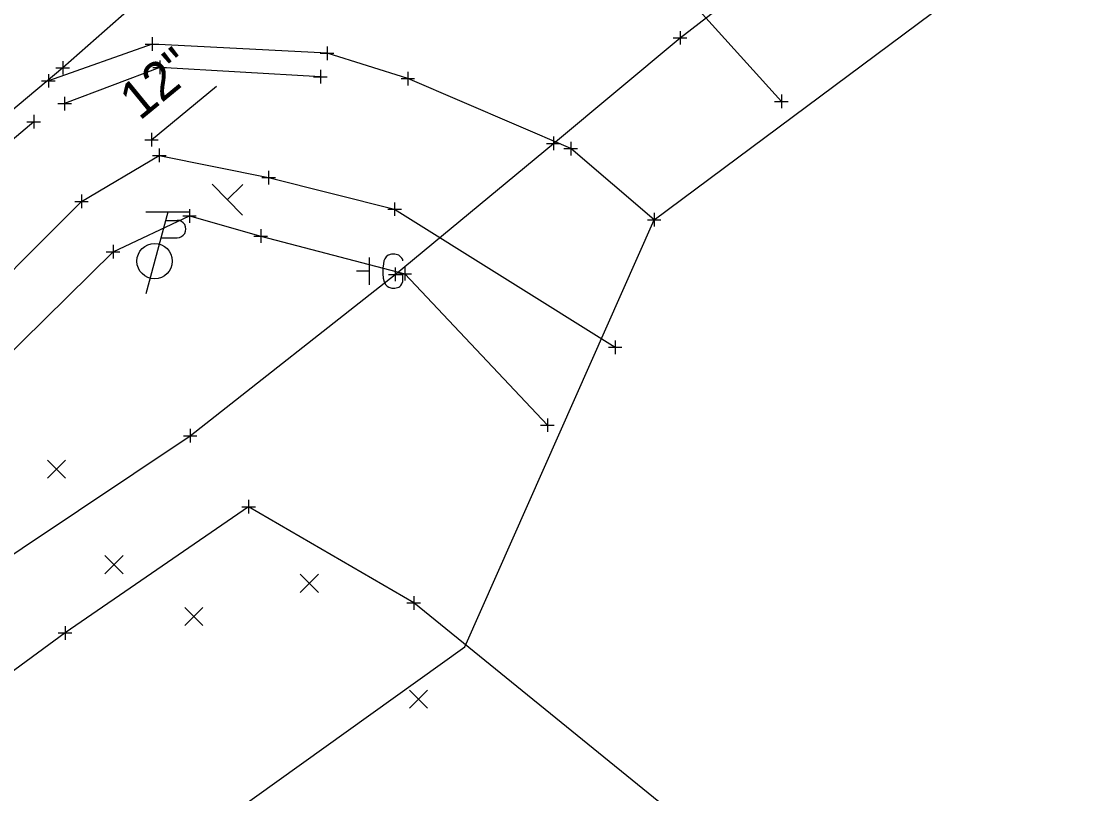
# Model space of a CAD drawing. Extents: x -4 to 139204, y -4 to 477121.
# Drawn here: x 139123.3 to 139201.5, y 476967.4 to 477024.3 of the extents above; entities that cross this region are included whole.
import ezdxf

# ---------------------------------------------------------------- set-up
doc = ezdxf.new("R2010")
doc.units = 0
for name, color, linetype in [('_CIVIL_CONSTRUCTION', 7, 'Continuous'), ('DR_X_Ditch', 7, 'Continuous'), ('DR_X_Storm_Sewer', 7, 'Continuous'), ('DR_X_Text', 7, 'Continuous'), ('DV_X_Property_Line', 7, 'Continuous'), ('GE_X_Alignment', 7, 'Continuous'), ('GE_X_Alignment_100_Bearings', 7, 'Continuous'), ('GE_X_Alignment_100_Cardinal_Points', 7, 'Continuous'), ('GE_X_Alignment_100_Distances', 7, 'Continuous'), ('PV_X_COP', 7, 'Continuous'), ('PV_X_Shoulder', 7, 'Continuous'), ('PV_X_Shoulder_Aggregate', 7, 'Continuous'), ('RD_X_Fence', 7, 'Continuous'), ('SC_Scratch1', 7, 'Continuous'), ('SV_X_Terrain_Boundary', 7, 'Continuous'), ('UT_X_Gas', 7, 'Continuous')]:
    doc.layers.add(name, color=color, linetype=linetype)

msp = doc.modelspace()

# ---------------------------------------------------------------- linework, layer by layer
at = {"layer": '_CIVIL_CONSTRUCTION'}
for p, q in [((139139.571, 477009.978), (139137.337, 477012.268)), ((139138.454, 477011.123), (139139.599, 477012.24))]:
    msp.add_line(p, q, dxfattribs=at)
at = {"layer": 'DR_X_Ditch'}
msp.add_lwpolyline([(139102.91, 476985.845), (139107.6, 476990.771), (139117.961, 477001.241), (139127.724, 477011.001), (139133.449, 477014.389), (139141.493, 477012.75), (139150.77, 477010.429), (139167.005, 477000.273)], dxfattribs=at)
at = {"layer": 'DR_X_Storm_Sewer'}
msp.add_line((139132.876, 477015.536), (139137.671, 477019.471), dxfattribs=at)
at = {"layer": 'DV_X_Property_Line'}
for p, q in [((139148.911, 477004.871), (139148.911, 477006.871)), ((139148.911, 477005.871), (139147.959, 477005.871))]:
    msp.add_line(p, q, dxfattribs=at)
msp.add_lwpolyline([(139151.388, 477006.627), (139151.368, 477006.726), (139151.309, 477006.824), (139151.21, 477006.922), (139151.073, 477007.041), (139150.974, 477007.08), (139150.895, 477007.099), (139150.777, 477007.119), (139150.541, 477007.119), (139150.443, 477007.099), (139150.384, 477007.08), (139150.305, 477007.041), (139150.147, 477006.922), (139150.049, 477006.785), (139149.99, 477006.627), (139149.951, 477006.411), (139149.911, 477006.096), (139149.911, 477005.682), (139149.931, 477005.348), (139150.01, 477005.092), (139150.128, 477004.856), (139150.226, 477004.777), (139150.344, 477004.698), (139150.561, 477004.619), (139150.777, 477004.619), (139150.994, 477004.659), (139151.073, 477004.698), (139151.151, 477004.737), (139151.23, 477004.816), (139151.309, 477004.934), (139151.388, 477005.112), (139151.388, 477005.604), (139150.974, 477005.604)], dxfattribs=at)
at = {"layer": 'GE_X_Alignment'}
for p, q in [((139125.216, 476990.64), (139126.55, 476991.976)), ((139125.216, 476991.976), (139126.55, 476990.64)), ((139129.447, 476983.611), (139130.781, 476984.946)), ((139129.447, 476984.946), (139130.781, 476983.611)), ((139143.828, 476982.239), (139145.162, 476983.574)), ((139143.828, 476983.574), (139145.162, 476982.239)), ((139135.322, 476979.794), (139136.656, 476981.129)), ((139135.322, 476981.129), (139136.656, 476979.794)), ((139151.864, 476973.716), (139153.198, 476975.052)), ((139151.864, 476975.052), (139153.198, 476973.716))]:
    msp.add_line(p, q, dxfattribs=at)
at = {"layer": 'GE_X_Alignment_100_Bearings'}
for p, q in [((139171.782, 477023.538), (139171.782, 477022.538)), ((139132.414, 477022.583), (139133.414, 477022.583)), ((139132.914, 477023.083), (139132.914, 477022.083)), ((139132.914, 477022.583), (139132.914, 477022.583)), ((139145.801, 477022.405), (139145.801, 477021.405)), ((139171.282, 477023.038), (139172.282, 477023.038)), ((139171.782, 477023.038), (139171.782, 477023.038)), ((139145.301, 477021.905), (139146.301, 477021.905)), ((139145.801, 477021.905), (139145.801, 477021.905)), ((139125.843, 477020.832), (139126.843, 477020.832)), ((139126.343, 477021.332), (139126.343, 477020.332)), ((139126.343, 477020.832), (139126.343, 477020.832)), ((139132.982, 477020.867), (139133.982, 477020.867)), ((139133.482, 477021.367), (139133.482, 477020.367)), ((139133.482, 477020.867), (139133.482, 477020.867)), ((139125.288, 477020.373), (139125.288, 477019.373)), ((139144.81, 477020.174), (139145.81, 477020.174)), ((139145.31, 477020.674), (139145.31, 477019.674)), ((139145.31, 477020.174), (139145.31, 477020.174)), ((139151.242, 477020.034), (139152.242, 477020.034)), ((139151.742, 477020.534), (139151.742, 477019.534)), ((139151.742, 477020.034), (139151.742, 477020.034)), ((139124.788, 477019.873), (139125.788, 477019.873)), ((139125.288, 477019.873), (139125.288, 477019.873)), ((139126.484, 477018.698), (139126.484, 477017.698)), ((139179.244, 477018.865), (139179.244, 477017.865)), ((139125.984, 477018.198), (139126.984, 477018.198)), ((139126.484, 477018.198), (139126.484, 477018.198)), ((139178.744, 477018.365), (139179.744, 477018.365)), ((139179.244, 477018.365), (139179.244, 477018.365)), ((139124.206, 477017.36), (139124.206, 477016.36)), ((139123.706, 477016.86), (139124.706, 477016.86)), ((139124.206, 477016.86), (139124.206, 477016.86)), ((139162.46, 477015.77), (139162.46, 477014.77)), ((139163.739, 477015.39), (139163.739, 477014.39)), ((139133.449, 477014.889), (139133.449, 477013.889)), ((139161.96, 477015.27), (139162.96, 477015.27)), ((139162.46, 477015.27), (139162.46, 477015.27)), ((139163.239, 477014.89), (139164.239, 477014.89)), ((139163.739, 477014.89), (139163.739, 477014.89)), ((139132.949, 477014.389), (139133.949, 477014.389)), ((139133.449, 477014.389), (139133.449, 477014.389)), ((139141.493, 477013.25), (139141.493, 477012.25)), ((139140.993, 477012.75), (139141.993, 477012.75)), ((139141.493, 477012.75), (139141.493, 477012.75)), ((139127.724, 477011.501), (139127.724, 477010.501)), ((139127.224, 477011.001), (139128.224, 477011.001)), ((139127.724, 477011.001), (139127.724, 477011.001)), ((139150.77, 477010.929), (139150.77, 477009.929)), ((139135.173, 477009.934), (139136.173, 477009.934)), ((139135.673, 477010.434), (139135.673, 477009.434)), ((139135.673, 477009.934), (139135.673, 477009.934)), ((139150.27, 477010.429), (139151.27, 477010.429)), ((139150.77, 477010.429), (139150.77, 477010.429)), ((139169.878, 477010.154), (139169.878, 477009.154)), ((139169.378, 477009.654), (139170.378, 477009.654)), ((139169.878, 477009.654), (139169.878, 477009.654)), ((139140.414, 477008.455), (139141.414, 477008.455)), ((139140.914, 477008.955), (139140.914, 477007.955)), ((139140.914, 477008.455), (139140.914, 477008.455)), ((139130.051, 477007.8), (139130.051, 477006.8)), ((139129.551, 477007.3), (139130.551, 477007.3)), ((139130.051, 477007.3), (139130.051, 477007.3)), ((139150.82, 477006.132), (139150.82, 477005.132)), ((139151.523, 477006.171), (139151.523, 477005.171)), ((139150.32, 477005.632), (139151.32, 477005.632)), ((139150.82, 477005.632), (139150.82, 477005.632)), ((139151.023, 477005.671), (139152.023, 477005.671)), ((139151.523, 477005.671), (139151.523, 477005.671)), ((139167.005, 477000.773), (139167.005, 476999.773)), ((139166.505, 477000.273), (139167.505, 477000.273)), ((139167.005, 477000.273), (139167.005, 477000.273)), ((139162.013, 476995.038), (139162.013, 476994.038)), ((139135.72, 476994.265), (139135.72, 476993.265)), ((139161.513, 476994.538), (139162.513, 476994.538)), ((139162.013, 476994.538), (139162.013, 476994.538)), ((139135.22, 476993.765), (139136.22, 476993.765)), ((139135.72, 476993.765), (139135.72, 476993.765)), ((139140.024, 476989.041), (139140.024, 476988.041)), ((139139.524, 476988.541), (139140.524, 476988.541)), ((139140.024, 476988.541), (139140.024, 476988.541)), ((139152.176, 476981.957), (139152.176, 476980.957)), ((139151.676, 476981.457), (139152.676, 476981.457)), ((139152.176, 476981.457), (139152.176, 476981.457)), ((139126.511, 476979.748), (139126.511, 476978.748)), ((139126.011, 476979.248), (139127.011, 476979.248)), ((139126.511, 476979.248), (139126.511, 476979.248))]:
    msp.add_line(p, q, dxfattribs=at)
at = {"layer": 'GE_X_Alignment_100_Cardinal_Points'}
for p, q in [((139134.069, 477010.208), (139132.463, 477004.208)), ((139135.669, 477010.208), (139132.469, 477010.208)), ((139133.909, 477009.608), (139134.759, 477009.608)), ((139133.568, 477008.333), (139134.759, 477008.333))]:
    msp.add_line(p, q, dxfattribs=at)
msp.add_circle((139133.106, 477006.608), 1.3, dxfattribs=at)
msp.add_arc((139134.772, 477008.97), 0.638, 268.8767, 91.1233, dxfattribs=at)
at = {"layer": 'GE_X_Alignment_100_Distances'}
for p, q in [((139132.376, 477015.536), (139133.376, 477015.536)), ((139132.876, 477016.036), (139132.876, 477015.036)), ((139132.876, 477015.536), (139132.876, 477015.536))]:
    msp.add_line(p, q, dxfattribs=at)
at = {"layer": 'PV_X_COP'}
msp.add_lwpolyline([(139154.971, 477045.177), (139166.025, 477033.005), (139179.244, 477018.365)], dxfattribs=at)
at = {"layer": 'PV_X_Shoulder'}
for points in [[(139183.638, 477072.424), (139153.919, 477045.299), (139136.787, 477030.023), (139126.343, 477020.832), (139109.649, 477006.831), (139097.905, 476996.885), (139077.102, 476979.89), (139059.387, 476965.891), (139020.106, 476935.561), (139003.351, 476922.965), (138997.924, 476918.666), (138993.965, 476914.098), (138990.512, 476910.309), (138981.306, 476903.856), (138956.564, 476885.614), (138940.343, 476873.773)], [(139169.878, 477009.654), (139163.739, 477014.89), (139151.742, 477020.034), (139145.801, 477021.905), (139132.914, 477022.583), (139125.288, 477019.873)]]:
    msp.add_lwpolyline(points, dxfattribs=at)
at = {"layer": 'PV_X_Shoulder_Aggregate'}
for points in [[(139145.31, 477020.174), (139133.482, 477020.867), (139126.484, 477018.198)], [(139124.206, 477016.86), (139110.781, 477005.495), (139098.924, 476995.454), (139078.061, 476978.654), (139060.667, 476964.123), (139021.044, 476934.127), (139004.817, 476921.429), (138999.267, 476916.949), (138995.343, 476912.815), (138991.494, 476909.144)]]:
    msp.add_lwpolyline(points, dxfattribs=at)
at = {"layer": 'RD_X_Fence'}
msp.add_lwpolyline([(139170.211, 476966.83), (139152.176, 476981.457), (139140.024, 476988.541), (139126.511, 476979.248), (139077.418, 476943.213), (139054.3, 476926.021), (139036.036, 476912.286), (139009.14, 476892.322), (138983.005, 476872.624), (138984.167, 476847.153), (138984.924, 476831.748)], dxfattribs=at)
at = {"layer": 'SC_Scratch1'}
msp.add_lwpolyline([(139107.799, 476980.817), (139110.645, 476986.989), (139121.64, 476999.018), (139130.051, 477007.3), (139135.673, 477009.934), (139140.914, 477008.455), (139151.523, 477005.671), (139162.013, 476994.538)], dxfattribs=at)
at = {"layer": 'SV_X_Terrain_Boundary'}
msp.add_lwpolyline([(139032.097, 476888.075), (139056.893, 476904.696), (139090.539, 476931.416), (139155.934, 476978.22), (139169.878, 477009.654), (139198.429, 477030.905), (139194.866, 477055.697), (139145.075, 477113.146), (139136.557, 477120.408), (139103.883, 477103.072), (139085.277, 477096.002), (139069.076, 477091.309), (139065.071, 477088.425), (139048.842, 477084.442), (139046.155, 477077.639), (139022.377, 477019.422)], dxfattribs=at)
at = {"layer": 'UT_X_Gas'}
msp.add_lwpolyline([(139004.075, 476900.734), (139028.392, 476919.279), (139049.353, 476936.04), (139135.72, 476993.765), (139150.82, 477005.632), (139162.46, 477015.27), (139171.782, 477023.038), (139186.18, 477034.164), (139199.281, 477045.473), (139201.496, 477047.37), (139194.822, 477055.784), (139186.687, 477066.39), (139182.688, 477071.332), (139173.257, 477082.641), (139163.808, 477093.452), (139160.449, 477097.743)], dxfattribs=at)

# ---------------------------------------------------------------- texts
at = {"layer": 'DR_X_Text'}
msp.add_text('12" ', height=2.8, rotation=39.36916, dxfattribs=at).set_placement((139132.005, 477016.893))

doc.saveas('drawing.dxf')
